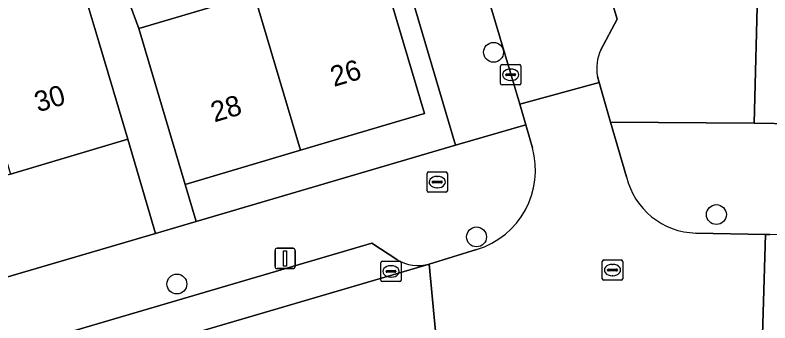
# Model space of a CAD drawing. Extents: x 162523 to 163266, y 381230 to 382050.
# Drawn here: x 162917.55 to 162954.65, y 381776.32 to 381791.47 of the extents above; entities that cross this region are included whole.
import ezdxf

# ---------------------------------------------------------------- set-up
doc = ezdxf.new("R2010")
doc.units = 0
for name, color, linetype in [('IMGEO_Boom', 7, 'Continuous'), ('IMGEO_Brandkraan', 7, 'Continuous'), ('IMGEO_Erf', 7, 'Continuous'), ('IMGEO_Kolk', 7, 'Continuous'), ('IMGEO_Lichtmast', 7, 'Continuous'), ('IMGEO_Pand', 7, 'Continuous'), ('IMGEO_Pand_nummerreeks', 7, 'Continuous'), ('IMGEO_Parkeervlak_open', 7, 'Continuous'), ('IMGEO_Rijbaan_lokaal_open', 7, 'Continuous'), ('IMGEO_Rioolput', 7, 'Continuous'), ('IMGEO_Voetpad_open', 7, 'Continuous')]:
    doc.layers.add(name, color=color, linetype=linetype)

msp = doc.modelspace()

# ---------------------------------------------------------------- linework, layer by layer
at = {"layer": 'IMGEO_Boom'}
for centre in [(162941.067, 381789.638), (162952.02, 381781.652), (162940.23, 381780.554), (162925.502, 381778.235)]:
    msp.add_circle(centre, 0.489, dxfattribs=at)
at = {"layer": 'IMGEO_Brandkraan'}
for p, q in [((162937.797, 381782.825), (162937.797, 381783.677)), ((162937.872, 381783.751), (162938.724, 381783.751)), ((162938.285, 381783.531), (162938.31, 381783.531)), ((162938.798, 381783.677), (162938.798, 381782.825)), ((162938.056, 381783.245), (162938.056, 381783.257)), ((162938.494, 381783.208), (162938.096, 381783.208)), ((162938.099, 381783.294), (162938.497, 381783.294)), ((162938.54, 381783.257), (162938.54, 381783.245)), ((162938.724, 381782.751), (162937.872, 381782.751)), ((162938.308, 381782.971), (162938.283, 381782.971))]:
    msp.add_line(p, q, dxfattribs=at)
for points in [[(162937.797, 381782.825), (162937.797, 381783.677)], [(162937.872, 381783.751), (162938.724, 381783.751)], [(162938.798, 381783.677), (162938.798, 381782.825)], [(162938.724, 381782.751), (162937.872, 381782.751)]]:
    msp.add_lwpolyline(points, dxfattribs=at)
for centre, radius, start, end in [((162937.874, 381783.675), 0.0765, 91.552, 178.448), ((162937.874, 381783.675), 0.0765, 91.552, 178.448), ((162938.722, 381783.675), 0.0765, 1.552, 88.448), ((162938.722, 381783.675), 0.0765, 1.552, 88.448), ((162938.096, 381783.254), 0.0403, 85.8775, 175.7526), ((162938.093, 381783.244), 0.0366, 178.938, 274.7102), ((162938.497, 381783.251), 0.043, 264.8664, 352.4533), ((162938.501, 381783.256), 0.0386, 1.7309, 96.639), ((162937.874, 381782.827), 0.0765, 181.552, 268.448), ((162937.874, 381782.827), 0.0765, 181.552, 268.448), ((162938.722, 381782.827), 0.0765, 271.552, 358.448), ((162938.722, 381782.827), 0.0765, 271.552, 358.448)]:
    msp.add_arc(centre, radius, start, end, dxfattribs=at)
for centre, major_axis, ratio, start_param, end_param in [((162938.284, 381783.251), (-0.387, 0.002), 0.722429, 4.712389, 7.853982), ((162938.309, 381783.251), (-0.39, 0.002), 0.717154, 1.570796, 4.712389)]:
    msp.add_ellipse(centre, major_axis=major_axis, ratio=ratio, start_param=start_param, end_param=end_param, dxfattribs=at)
at = {"layer": 'IMGEO_Erf'}
for points in [[(162935.387, 381794.303), (162937.67, 381786.625), (162931.58, 381784.814), (162925.911, 381783.129), (162926.444, 381781.315), (162939.195, 381785.063), (162936.402, 381794.569), (162934.087, 381802.294), (162927.962, 381800.514), (162927.072, 381803.576), (162919.725, 381801.432), (162919.923, 381800.847), (162920.486, 381799.008), (162920.602, 381799.044), (162923.628, 381790.807), (162929.298, 381792.493)], [(162983.304, 381795.054), (162983.253, 381792.555), (162977.318, 381792.677), (162971.15, 381792.804), (162965.164, 381792.927), (162959.075, 381793.053), (162954.052, 381793.156), (162953.874, 381786.148), (162989.552, 381785.568)], [(162924.45, 381780.729), (162923.088, 381785.363), (162917.325, 381783.649), (162911.591, 381781.944), (162905.786, 381780.218), (162899.852, 381778.454), (162894.028, 381776.722), (162895.389, 381772.188)]]:
    msp.add_lwpolyline(points, close=True, dxfattribs=at)
at = {"layer": 'IMGEO_Kolk'}
for p, q in [((162941.407, 381788.108), (162941.407, 381788.96)), ((162941.482, 381789.034), (162942.334, 381789.034)), ((162941.895, 381788.814), (162941.92, 381788.814)), ((162942.408, 381788.96), (162942.408, 381788.108)), ((162941.666, 381788.528), (162941.666, 381788.54)), ((162942.104, 381788.491), (162941.706, 381788.491)), ((162941.709, 381788.577), (162942.107, 381788.577)), ((162942.15, 381788.54), (162942.15, 381788.528)), ((162942.334, 381788.034), (162941.482, 381788.034)), ((162941.918, 381788.254), (162941.893, 381788.254)), ((162935.525, 381778.431), (162935.525, 381779.283)), ((162935.6, 381779.357), (162936.452, 381779.357)), ((162936.013, 381779.137), (162936.038, 381779.137)), ((162936.526, 381779.283), (162936.526, 381778.431)), ((162935.784, 381778.851), (162935.784, 381778.863)), ((162936.222, 381778.814), (162935.824, 381778.814)), ((162935.827, 381778.9), (162936.225, 381778.9)), ((162936.268, 381778.863), (162936.268, 381778.851)), ((162936.452, 381778.357), (162935.6, 381778.357)), ((162936.036, 381778.577), (162936.011, 381778.577))]:
    msp.add_line(p, q, dxfattribs=at)
for points in [[(162941.407, 381788.108), (162941.407, 381788.96)], [(162941.482, 381789.034), (162942.334, 381789.034)], [(162942.408, 381788.96), (162942.408, 381788.108)], [(162942.334, 381788.034), (162941.482, 381788.034)], [(162935.525, 381778.431), (162935.525, 381779.283)], [(162935.6, 381779.357), (162936.452, 381779.357)], [(162936.526, 381779.283), (162936.526, 381778.431)], [(162936.452, 381778.357), (162935.6, 381778.357)]]:
    msp.add_lwpolyline(points, dxfattribs=at)
for centre, radius, start, end in [((162941.484, 381788.958), 0.0765, 91.552, 178.448), ((162941.484, 381788.958), 0.0765, 91.552, 178.448), ((162942.332, 381788.958), 0.0765, 1.552, 88.448), ((162942.332, 381788.958), 0.0765, 1.552, 88.448), ((162941.706, 381788.537), 0.0403, 85.8775, 175.7526), ((162941.703, 381788.527), 0.0366, 178.938, 274.7102), ((162942.107, 381788.534), 0.043, 264.8664, 352.4533), ((162942.111, 381788.539), 0.0386, 1.7309, 96.639), ((162941.484, 381788.11), 0.0765, 181.552, 268.448), ((162941.484, 381788.11), 0.0765, 181.552, 268.448), ((162942.332, 381788.11), 0.0765, 271.552, 358.448), ((162942.332, 381788.11), 0.0765, 271.552, 358.448), ((162935.602, 381779.281), 0.0765, 91.552, 178.448), ((162935.602, 381779.281), 0.0765, 91.552, 178.448), ((162936.45, 381779.281), 0.0765, 1.552, 88.448), ((162936.45, 381779.281), 0.0765, 1.552, 88.448), ((162935.824, 381778.86), 0.0403, 85.8775, 175.7526), ((162935.821, 381778.85), 0.0366, 178.938, 274.7102), ((162936.225, 381778.857), 0.043, 264.8664, 352.4533), ((162936.229, 381778.862), 0.0386, 1.7309, 96.639), ((162935.602, 381778.433), 0.0765, 181.552, 268.448), ((162935.602, 381778.433), 0.0765, 181.552, 268.448), ((162936.45, 381778.433), 0.0765, 271.552, 358.448), ((162936.45, 381778.433), 0.0765, 271.552, 358.448)]:
    msp.add_arc(centre, radius, start, end, dxfattribs=at)
for centre, major_axis, ratio, start_param, end_param in [((162941.894, 381788.534), (-0.387, 0.002), 0.722429, 4.712389, 7.853982), ((162941.919, 381788.534), (-0.39, 0.002), 0.717154, 1.570796, 4.712389), ((162936.012, 381778.857), (-0.387, 0.002), 0.722429, 4.712389, 7.853982), ((162936.037, 381778.857), (-0.39, 0.002), 0.717154, 1.570796, 4.712389)]:
    msp.add_ellipse(centre, major_axis=major_axis, ratio=ratio, start_param=start_param, end_param=end_param, dxfattribs=at)
at = {"layer": 'IMGEO_Lichtmast'}
for p, q in [((162930.325, 381779.092), (162930.325, 381779.892)), ((162930.325, 381779.892), (162930.325, 381779.092)), ((162930.425, 381779.992), (162931.215, 381779.992)), ((162931.215, 381779.992), (162930.425, 381779.992)), ((162931.315, 381779.892), (162931.315, 381779.092)), ((162931.315, 381779.092), (162931.315, 381779.892)), ((162931.215, 381778.992), (162930.425, 381778.992)), ((162930.425, 381778.992), (162931.215, 381778.992))]:
    msp.add_line(p, q, dxfattribs=at)
msp.add_lwpolyline([(162930.745, 381779.867), (162930.895, 381779.867), (162930.895, 381779.117), (162930.745, 381779.117), (162930.745, 381779.867)], dxfattribs=at)
for centre, start, end in [((162930.425, 381779.892), 90, 180), ((162930.425, 381779.892), 90, 180), ((162931.215, 381779.892), 0, 90), ((162931.215, 381779.892), 360, 90), ((162930.425, 381779.092), 180, 270), ((162930.425, 381779.092), 180, 270), ((162931.215, 381779.092), 270, 0), ((162931.215, 381779.092), 270, 0)]:
    msp.add_arc(centre, 0.1, start, end, dxfattribs=at)
at = {"layer": 'IMGEO_Pand'}
for points in [[(162931.58, 381784.814), (162937.67, 381786.625), (162935.387, 381794.303), (162929.298, 381792.493)], [(162914.945, 381791.588), (162917.325, 381783.649), (162923.088, 381785.363), (162921.663, 381790.156), (162920.828, 381792.963), (162915.185, 381791.285), (162915.083, 381791.629)], [(162931.58, 381784.814), (162929.298, 381792.493), (162923.628, 381790.807), (162925.911, 381783.129)]]:
    msp.add_lwpolyline(points, close=True, dxfattribs=at)
at = {"layer": 'IMGEO_Parkeervlak_open'}
for points in [[(162936.318, 381779.438), (162935.089, 381780.24), (162902.131, 381770.55), (162901.283, 381768.994)], [(162900.263, 381768.158), (162937.902, 381779.218)]]:
    msp.add_lwpolyline(points, dxfattribs=at)
msp.add_arc((162937.364, 381781.158), 2.013, 238.6908, 285.4949, dxfattribs=at)
at = {"layer": 'IMGEO_Rijbaan_lokaal_open'}
for points in [[(162946.337, 381789.764), (162947.14, 381791.276), (162946.232, 381794.364), (162943.251, 381805.194), (162942.322, 381808.313), (162935.521, 381831.16), (162928.526, 381854.515), (162924.919, 381866.714)], [(162919.376, 381864.437), (162923.481, 381850.642), (162929.495, 381830.491), (162935.047, 381811.667), (162939.272, 381797.593), (162940.933, 381791.879), (162942.362, 381787.078), (162946.251, 381788.155), (162946.175, 381788.444)], [(162947.604, 381783.509), (162946.82, 381786.201), (162946.251, 381788.155), (162942.362, 381787.078), (162942.653, 381786.062), (162942.862, 381785.334), (162942.973, 381784.945)], [(162954.27, 381775.179), (162954.429, 381780.672), (162951.011, 381780.742)], [(162988.621, 381779.946), (162987.671, 381779.97), (162954.65, 381780.67), (162954.429, 381780.672), (162954.27, 381775.179), (162963.739, 381774.97), (162976.265, 381774.685), (162988.222, 381774.437)], [(162940.236, 381779.933), (162937.902, 381779.218), (162938.434, 381773.651), (162941.551, 381774.377), (162943.357, 381774.697)], [(162925.709, 381769.905), (162938.434, 381773.651), (162937.902, 381779.218), (162900.263, 381768.158), (162900.035, 381768.094), (162901.818, 381762.048), (162909.783, 381764.393), (162923.896, 381768.968)]]:
    msp.add_lwpolyline(points, dxfattribs=at)
for centre, radius, start, end in [((162948.278, 381788.856), 2.142, 154.9219, 191.0845), ((162939.055, 381783.831), 4.073, 286.8512, 15.8718), ((162951.106, 381784.34), 3.599, 193.3476, 268.4887)]:
    msp.add_arc(centre, radius, start, end, dxfattribs=at)
at = {"layer": 'IMGEO_Rioolput'}
for p, q in [((162946.487, 381779.423), (162947.339, 381779.423)), ((162946.412, 381778.497), (162946.412, 381779.349)), ((162946.9, 381779.203), (162946.925, 381779.203)), ((162947.413, 381779.349), (162947.413, 381778.497)), ((162946.671, 381778.917), (162946.671, 381778.929)), ((162947.109, 381778.88), (162946.711, 381778.88)), ((162946.714, 381778.966), (162947.112, 381778.966)), ((162947.155, 381778.929), (162947.155, 381778.917)), ((162947.339, 381778.423), (162946.487, 381778.423)), ((162946.923, 381778.643), (162946.898, 381778.643))]:
    msp.add_line(p, q, dxfattribs=at)
for points in [[(162946.487, 381779.423), (162947.339, 381779.423)], [(162946.412, 381778.497), (162946.412, 381779.349)], [(162947.413, 381779.349), (162947.413, 381778.497)], [(162947.339, 381778.423), (162946.487, 381778.423)]]:
    msp.add_lwpolyline(points, dxfattribs=at)
for centre, radius, start, end in [((162946.489, 381779.347), 0.0765, 91.552, 178.448), ((162946.489, 381779.347), 0.0765, 91.552, 178.448), ((162947.337, 381779.347), 0.0765, 1.552, 88.448), ((162947.337, 381779.347), 0.0765, 1.552, 88.448), ((162946.711, 381778.926), 0.0403, 85.8775, 175.7526), ((162946.708, 381778.916), 0.0366, 178.938, 274.7102), ((162947.112, 381778.923), 0.043, 264.8664, 352.4533), ((162947.116, 381778.928), 0.0386, 1.7309, 96.639), ((162946.489, 381778.499), 0.0765, 181.552, 268.448), ((162946.489, 381778.499), 0.0765, 181.552, 268.448), ((162947.337, 381778.499), 0.0765, 271.552, 358.448), ((162947.337, 381778.499), 0.0765, 271.552, 358.448)]:
    msp.add_arc(centre, radius, start, end, dxfattribs=at)
for centre, major_axis, ratio, start_param, end_param in [((162946.899, 381778.923), (-0.387, 0.002), 0.722429, 4.712389, 7.853982), ((162946.924, 381778.923), (-0.39, 0.002), 0.717154, 1.570796, 4.712389)]:
    msp.add_ellipse(centre, major_axis=major_axis, ratio=ratio, start_param=start_param, end_param=end_param, dxfattribs=at)
at = {"layer": 'IMGEO_Voetpad_open'}
for points in [[(162942.548, 381907.783), (162932.776, 381896.712), (162917.749, 381879.811), (162913.026, 381874.412), (162932.72, 381806.989), (162933.197, 381805.356), (162934.087, 381802.294), (162936.402, 381794.569), (162939.195, 381785.063), (162942.653, 381786.062), (162942.362, 381787.078), (162940.933, 381791.879)], [(162924.919, 381866.714), (162928.526, 381854.515), (162935.521, 381831.16), (162942.322, 381808.313), (162942.8, 381808.456), (162943.729, 381805.337), (162943.251, 381805.194), (162946.232, 381794.364), (162947.14, 381791.276), (162946.337, 381789.764)], [(162946.175, 381788.444), (162946.251, 381788.155), (162946.82, 381786.201), (162953.874, 381786.148), (162954.052, 381793.156), (162954.122, 381796.578), (162951.912, 381796.623), (162951.914, 381796.703), (162947.198, 381796.703), (162945.842, 381801.764)], [(162920.828, 381792.963), (162921.663, 381790.156), (162923.088, 381785.363), (162924.45, 381780.729), (162926.444, 381781.315), (162925.911, 381783.129), (162923.628, 381790.807), (162920.602, 381799.044)], [(162953.874, 381786.148), (162946.82, 381786.201), (162947.604, 381783.509)], [(162989.552, 381785.568), (162953.874, 381786.148)], [(162942.973, 381784.945), (162942.862, 381785.334), (162942.653, 381786.062), (162939.195, 381785.063), (162926.444, 381781.315), (162924.45, 381780.729), (162895.389, 381772.188), (162891.48, 381770.937)], [(162951.011, 381780.742), (162954.429, 381780.672), (162954.65, 381780.67)], [(162901.283, 381768.994), (162902.131, 381770.55), (162935.089, 381780.24)], [(162935.089, 381780.24), (162936.318, 381779.438)], [(162937.902, 381779.218), (162940.236, 381779.933)]]:
    msp.add_lwpolyline(points, dxfattribs=at)
for centre, radius, start, end in [((162948.278, 381788.856), 2.142, 154.9219, 191.0845), ((162939.055, 381783.831), 4.073, 286.8512, 15.8718), ((162951.106, 381784.34), 3.599, 193.3476, 268.4887), ((162937.364, 381781.158), 2.013, 238.6908, 285.4949)]:
    msp.add_arc(centre, radius, start, end, dxfattribs=at)

# ---------------------------------------------------------------- texts
at = {"layer": 'IMGEO_Pand_nummerreeks'}
for s, rotation, p in [('26', 16.5574, (162933.22, 381787.931)), ('30', 16.5599, (162918.674, 381786.68)), ('28', 16.5574, (162927.343, 381786.184))]:
    msp.add_text(s, height=1, rotation=rotation, dxfattribs=at).set_placement(p)

doc.saveas('drawing.dxf')
